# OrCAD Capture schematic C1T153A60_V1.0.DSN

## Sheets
1 01_Main: size A4; title: Telink-Semi; rev: V1.0; note: C1T153A60
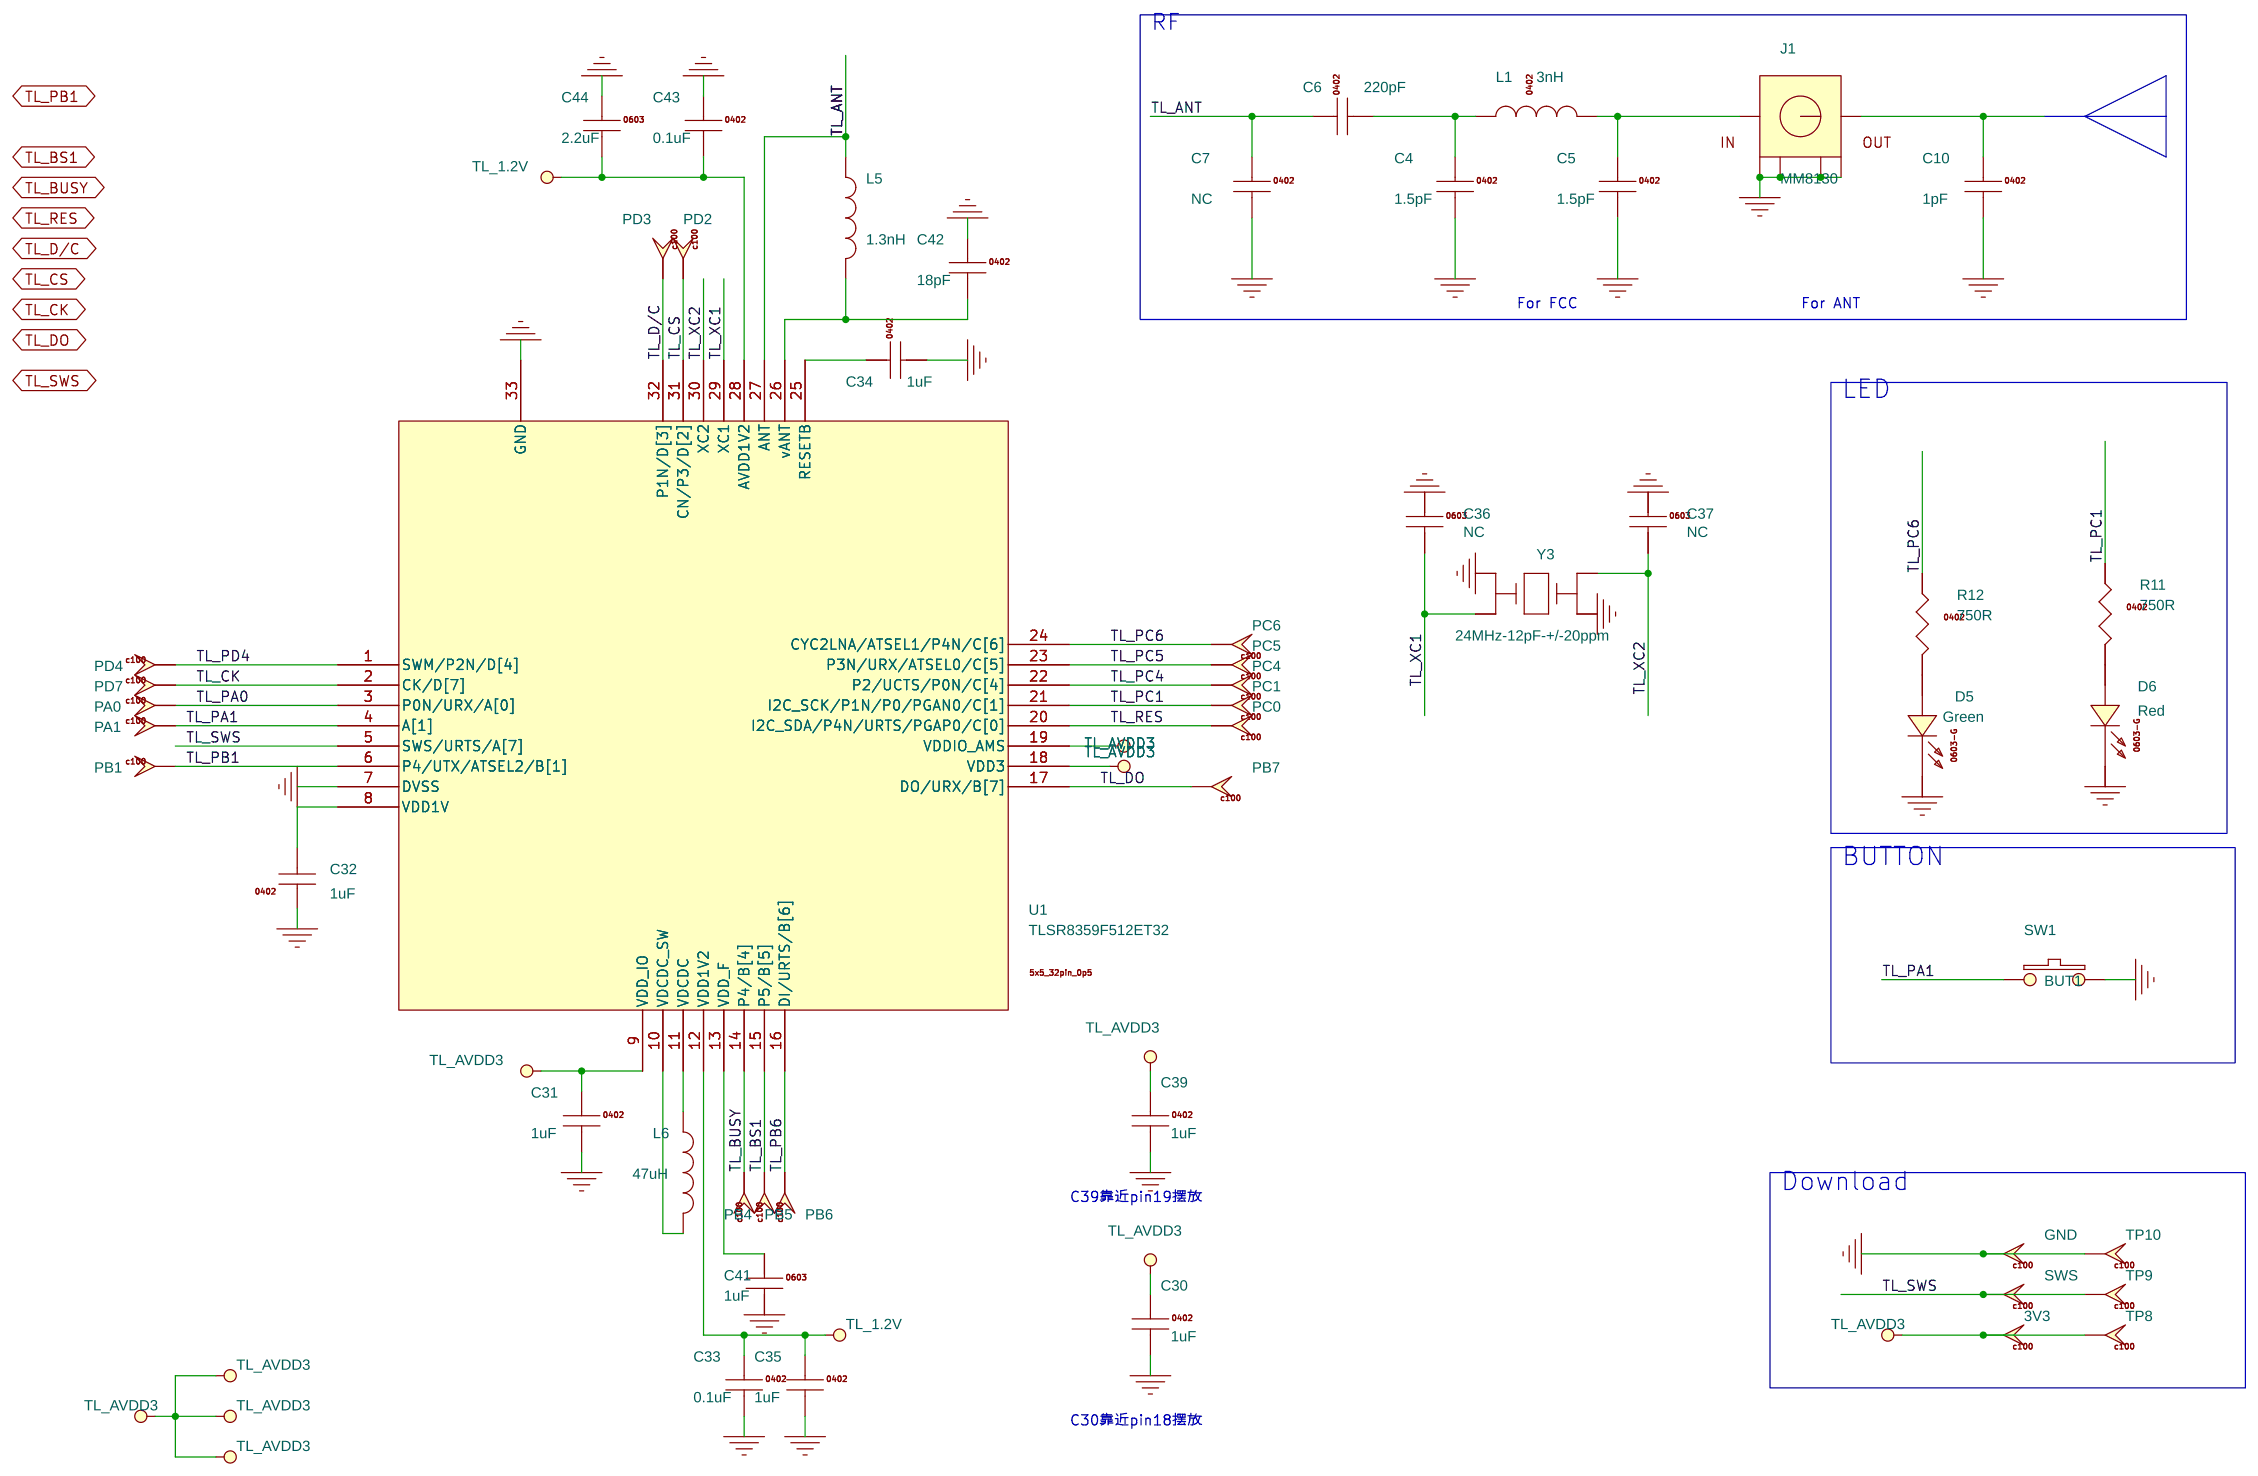
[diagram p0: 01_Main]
2 02_Display: size A4
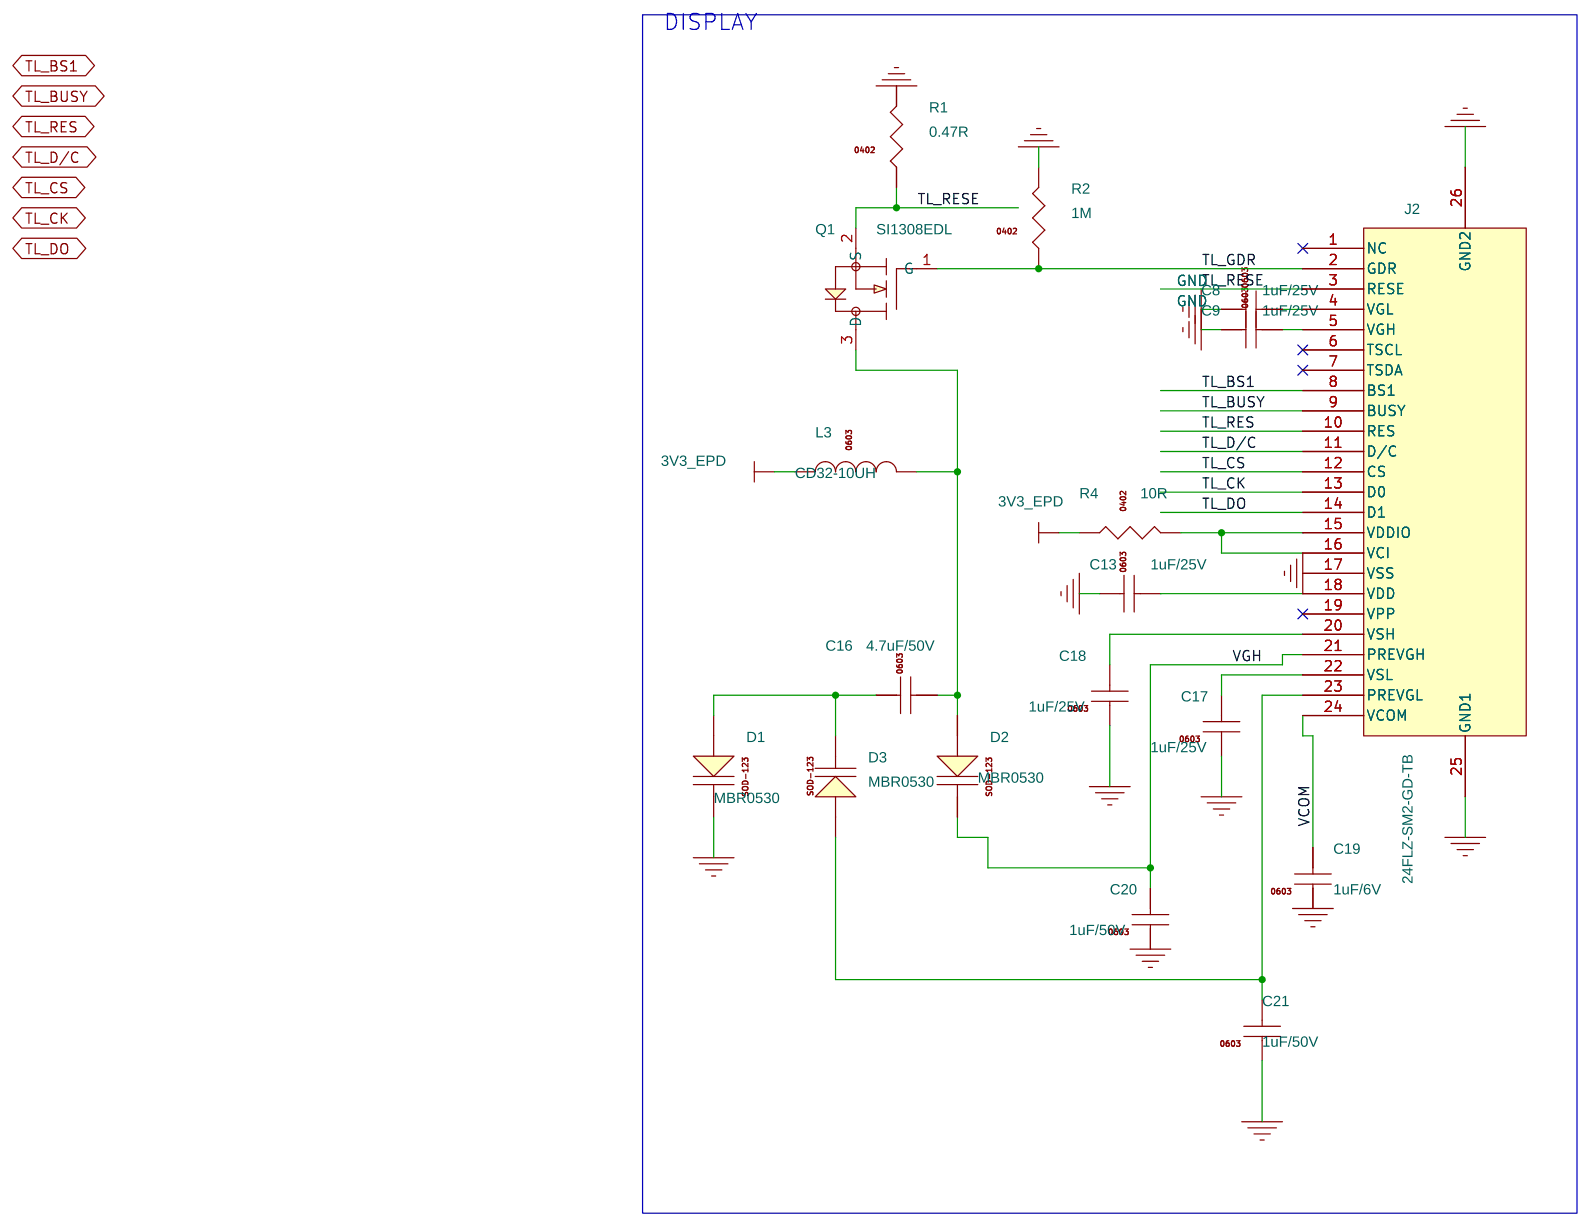
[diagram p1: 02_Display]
3 03_Power: size A4
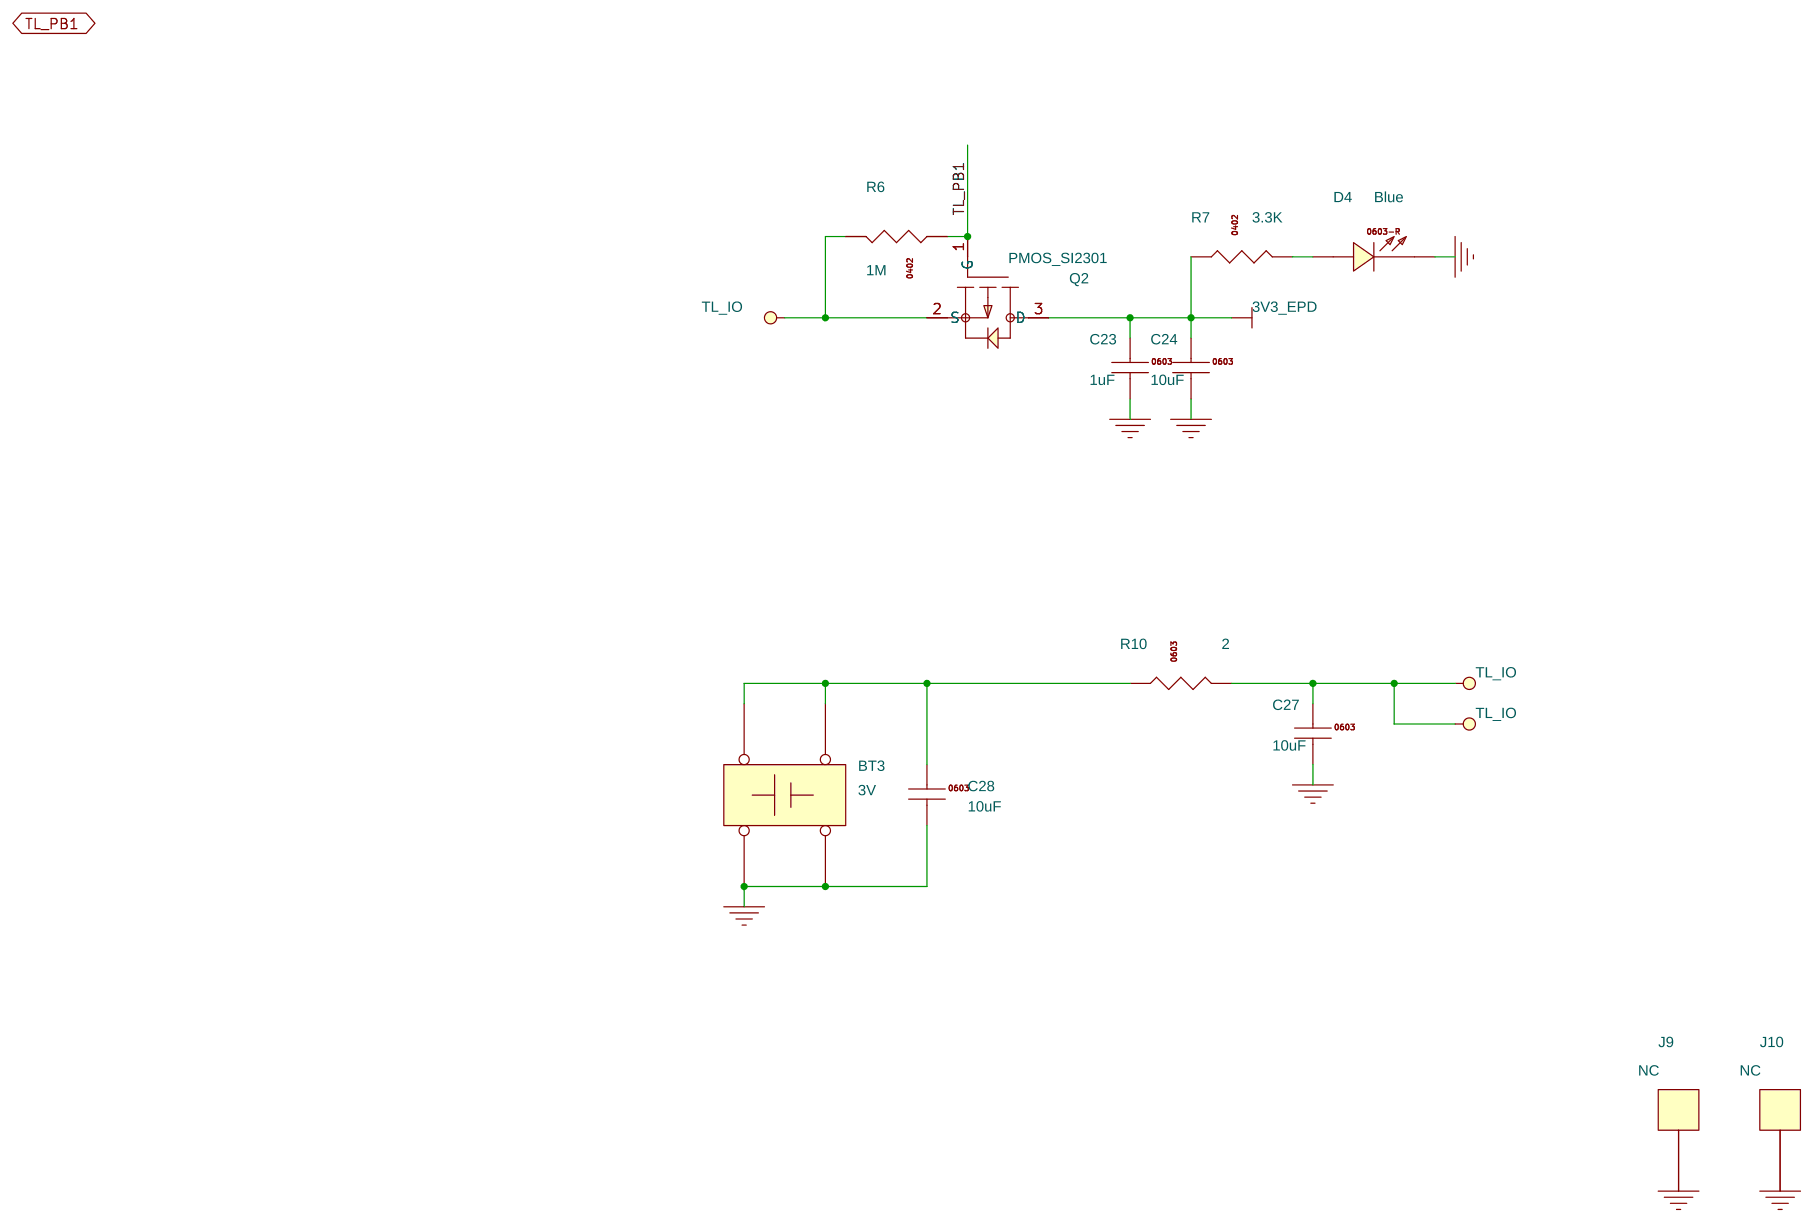
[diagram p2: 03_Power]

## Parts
sheet 01_Main
3V3  TP  [TP100]
C4  1.5pF  [0402]
C5  1.5pF  [0402]
C6  220pF  [0402]
C7  NC  [0402]
C10  1pF  [0402]
C30  1uF  [0402]
C31  1uF  [0402]
C32  1uF  [0402]
C33  0.1uF  [0402]
C34  1uF  [0402]
C35  1uF  [0402]
C36  NC  [0402]
C37  NC  [0402]
C39  1uF  [0402]
C41  1uF  [0603C]
C42  18pF  [0402]
C43  0.1uF  [0402]
C44  2.2uF  [0603C]
D5  Green  [0603-LED]
D6  Red  [0603-LED]
GND  TP  [TP100]
J1  MM8130  [MM8130-2600]
L1  3nH  [0402]
L5  1.3nH  [0402]
L6  47uH  [0805L]
PA0  TP  [TP100]
PA1  TP  [TP100]
PB1  TP  [TP100]
PB4  TP  [TP100]
PB5  TP  [TP100]
PB6  TP  [TP100]
PB7  TP  [TP100]
PC0  TP  [TP100]
PC1  TP  [TP100]
PC4  TP  [TP100]
PC5  TP  [TP100]
PC6  TP  [TP100]
PD2  TP  [TP100]
PD3  TP  [TP100]
PD4  TP  [TP100]
PD7  TP  [TP100]
R11  750R  [0402]
R12  750R  [0402]
SW1  BUT1  [butsmd2px4_00y3_00_nh]
SWS  TP  [TP100]
TP8  TP  [TP100]
TP9  TP  [TP100]
TP10  TP  [TP100]
U1  TLSR8359F512ET32  [qfn_5x5_32pin_0p5_2p50x2p50]
Y3  24MHz-12pF-+/-20ppm  [OSCCC250X320X110]
sheet 02_Display
C8  1uF/25V  [0603C]
C9  1uF/25V  [0603C]
C13  1uF/25V  [0402]
C16  4.7uF/50V  [0603C]
C17  1uF/25V  [0603C]
C18  1uF/25V  [0603C]
C19  1uF/6V  [0603C]
C20  1uF/50V  [0603C]
C21  1uF/50V  [0603C]
D1  MBR0530  [sod-123]
D2  MBR0530  [sod-123]
D3  MBR0530  [sod-123]
J2  24FLZ-SM2-GD-TB  [fpc_24pin]
L3  CD32-10UH  [cd32]
Q1  SI1308EDL  [sot-323]
R1  0.47R  [0402]
R2  1M  [0402]
R4  10R  [0402]
sheet 03_Power
BT3  3V  [BAT_P1]
C23  1uF  [0603C]
C24  10uF  [0603C]
C27  10uF  [0603C]
C28  10uF  [0805C]
D4  Blue  [0603-LED]
J9  NC  [HDR254F-1X1X850]
J10  NC  [HDR254F-1X1X850]
Q2  PMOS_SI2301  [mos_sot-23]
R6  1M  [0603r]
R7  3.3K  [0603r]
R10  2  [0603R]

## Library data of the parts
3V3 GND PA0 PA1 PB1 PB4-PB7 PC0 PC1 PC4-PC6 PD2-PD4 PD7 SWS TP8-TP10 = TestPad100
C4-C7 C10 = C1005_NC
C30 = C1005X5R1C105K_1
C31 C33 C35 C42 C43 = C1005X5R1C105K_0
C32 C34 = C1005X5R1C105K
C13 C16-C21 C36 C37 C41 C44 = C1608_NC
C39 = C1005X5R1C105K_3
D5 D6 = 0603D_Green
J1 = MM8130_1
L1 = MLK1005S2N2ST
L5 L6 = IND_0
R11 R12 = RS0402K102JT
SW1 = SW_PUSHBUTTON-SPST_SM
U1 = TLSR8359F512ET32
Y3 = CRYSTAL4_SM_0
C8 C9 C23 C24 = C1608X5R1C105M
D1-D3 = Diode_CDBW0520L-G
J2 = CON_2.54mm_1x24
L3 = MLK1608S4N7ST
Q1 = NMOS_SI2302
R1 R2 R4 = RS0402K000JT
BT3 = SW_SL_DPDT_2
C27 C28 = C1608X5R0J106M
D4 = 0603D_Red
J9 J10 = CON1
Q2 = PMOS_SI2301
R6 = RS0402K105JT
R7 = RS0402K332JT
R10 = RS0603K020JT

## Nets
3V3_EPD: C23.1 C24.1 L3.1 Q2.3(D) R4.1 R7.1
GND: BT3.1 BT3.3 C4.2 C5.2 C7.2 C8.1 C9.1 C10.2 C13.1 C17.1 C18.1 C19.1 C20.1 C21.1 C23.2 C24.2 C27.2 C28.2 C30.2 C31.2 C32.1 C33.2 C34.2 C35.2 C36.1 C37.1 C39.2 C41.2 C42.1 C43.1 C44.1 D1.C D4.C(CATHODE) D5.C(CATHODE) D6.C(CATHODE) GND.1(TP) J1.3 J1.4 J1.5 J1.6 J2.17(VSS) J2.25(GND1) J2.26(GND2) J9.1 J10.1 R1.2 R2.2 SW1.2 TP10.1(TP) U1.7(DVSS) U1.33(GND) Y3.2 Y3.4
TL_1.2V: C33.1 C35.1 C43.2 C44.2 U1.12(VDD1V2) U1.28(AVDD1V2)
TL_3V3: 3V3.1(TP) C27.1 C30.1 C31.1 C39.1 Q2.2(S) R6.2 R10.2 TP8.1(TP) U1.9(VDD_IO) U1.18(VDD3) U1.19(VDDIO_AMS)
TL_ANT: C6.1 C7.1 L5.1 U1.27(ANT)
TL_BS1: PB5.1(TP) U1.15(P5/B[5])
TL_BS1 (page 02_Display): J2.8(BS1)
TL_BUSY: PB4.1(TP) U1.14(P4/B[4])
TL_BUSY (page 02_Display): J2.9(BUSY)
TL_CK: PD7.1(TP) U1.2(CK/D[7])
TL_CK (page 02_Display): J2.13(D0)
TL_CS: PD2.1(TP) U1.31(CN/P3/D[2])
TL_CS (page 02_Display): J2.12(CS)
TL_D/C: PD3.1(TP) U1.32(P1N/D[3])
TL_D/C (page 02_Display): J2.11(D/C)
TL_DO: PB7.1(TP) U1.17(DO/URX/B[7])
TL_DO (page 02_Display): J2.14(D1)
TL_GDR: J2.2(GDR) Q1.1(G) R2.1
TL_PA0: PA0.1(TP) U1.3(P0N/URX/A[0])
TL_PA1: PA1.1(TP) SW1.1 U1.4(A[1])
TL_PB1: PB1.1(TP) U1.6(P4/UTX/ATSEL2/B[1])
TL_PB1 (page 03_Power): Q2.1(G) R6.1
TL_PB6: PB6.1(TP) U1.16(DI/URTS/B[6])
TL_PC1: PC1.1(TP) R11.1 U1.21(I2C_SCK/P1N/P0/PGAN0/C[1])
TL_PC4: PC4.1(TP) U1.22(P2/UCTS/P0N/C[4])
TL_PC5: PC5.1(TP) U1.23(P3N/URX/ATSEL0/C[5])
TL_PC6: PC6.1(TP) R12.1 U1.24(CYC2LNA/ATSEL1/P4N/C[6])
TL_PD4: PD4.1(TP) U1.1(SWM/P2N/D[4])
TL_RES: PC0.1(TP) U1.20(I2C_SDA/P4N/URTS/PGAP0/C[0])
TL_RES (page 02_Display): J2.10(RES)
TL_RESE: J2.3(RESE) Q1.2(S) R1.1
TL_SWS: SWS.1(TP) TP9.1(TP) U1.5(SWS/URTS/A[7])
TL_XC1: C36.2 U1.29(XC1) Y3.3
TL_XC2: C37.2 U1.30(XC2) Y3.1
VCOM: C19.2 J2.24(VCOM)
VGH: C20.2 D2.C J2.21(PREVGH)
N14875219: C5.1 J1.1 L1.2
N14875301: C4.1 C6.2 L1.1
N14928293: C10.1 J1.2
N14941163: C32.2 U1.8(VDD1V)
N14941231: L6.1 U1.11(VDCDC)
N14941235: L6.2 U1.10(VDCDC_SW)
N14941343: C41.1 U1.13(VDD_F)
N14941393: C34.1 U1.25(RESETB)
N14941421: C42.2 L5.2 U1.26(vANT)
N14943903: C13.2 J2.18(VDD)
N14944011: J2.15(VDDIO) J2.16(VCI) R4.2
N14944019: C8.2 J2.4(VGL)
N14944031: C9.2 J2.5(VGH)
N14944091: C21.2 D3.A J2.23(PREVGL)
N14944123: C17.2 J2.22(VSL)
N14944143: C18.2 J2.20(VSH)
N14944227: C16.2 D2.A L3.2 Q1.3(D)
N14944235: C16.1 D1.A D3.C
N14952885: BT3.2 BT3.4 C28.1 R10.1
N14956435: D4.A(ANODE) R7.2
N14965797: D5.A(ANODE) R12.2
N14965806: D6.A(ANODE) R11.2

Not connected (* = marked no-connect by the designer): J2 1(NC)* 6(TSCL)* 7(TSDA)* 19(VPP)*

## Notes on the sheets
sheet 1
- RF
- For FCC
- For ANT
- LED
- BUTTON
- Download
- C39靠近pin19摆放
- C30靠近pin18摆放
sheet 2
- DISPLAY
